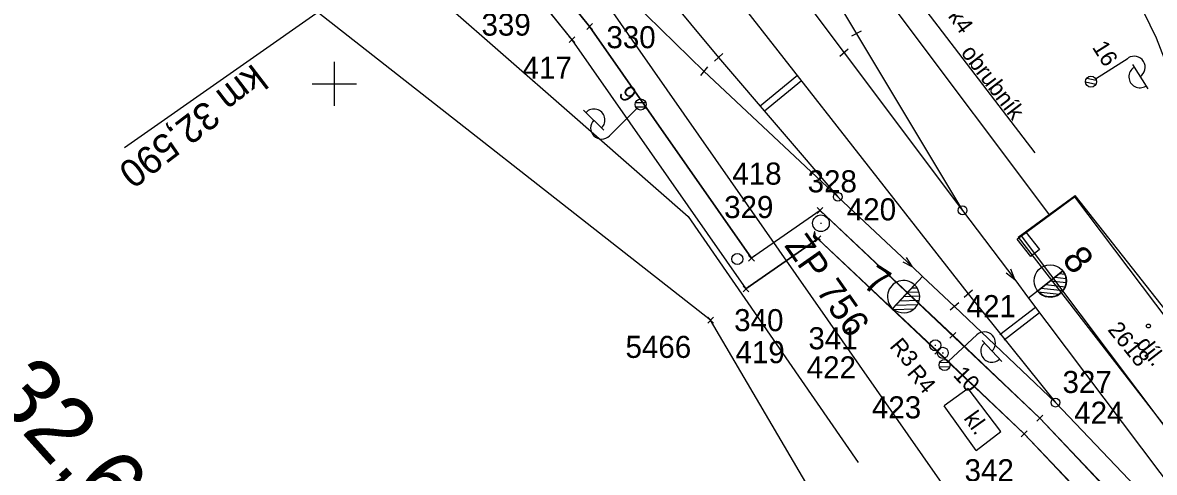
# Model space of a CAD drawing. Extents: x -804166 to -803706, y -1151030 to -1150147.
# Drawn here: x -804028.2 to -803925.7, y -1150435.2 to -1150394.5 of the extents above; entities that cross this region are included whole.
import ezdxf

# ---------------------------------------------------------------- set-up
doc = ezdxf.new("R2010")
doc.units = 0
for name, color, linetype in [('0381KM032-037P - Vrstva 1', 7, 'Continuous'), ('0381KM032-037P - Vrstva 2', 7, 'Continuous'), ('0381KM032-037P - Vrstva 23', 7, 'Continuous'), ('0381KM032-037P - Vrstva 25', 7, 'Continuous'), ('0381KM032-037P - Vrstva 27', 7, 'Continuous'), ('0381KM032-037P - Vrstva 3', 7, 'Continuous'), ('0381KM032-037P - Vrstva 36', 7, 'Continuous'), ('0381KM032-037P - Vrstva 4', 7, 'Continuous'), ('0381KM032-037P - Vrstva 49', 7, 'Continuous'), ('0381KM032-037P - Vrstva 51', 7, 'Continuous'), ('0381KM032-037P - Vrstva 55', 7, 'Continuous'), ('0381KM032-037P - Vrstva 57', 7, 'Continuous'), ('0381KM032-037P - Vrstva 59', 7, 'Continuous'), ('0381KM032-037P - Vrstva 7', 7, 'Continuous'), ('DZ_CD - CD', 7, 'Continuous'), ('DZ_CD - CD_krizek', 7, 'Continuous'), ('DZ_CD - CD_čísla', 7, 'Continuous'), ('krizky_1000 - Vrstva 1', 7, 'Continuous'), ('szdc - hran DP', 7, 'Continuous'), ('szdc - szdc_cislo', 7, 'Continuous'), ('szdc - szdc_krizek', 7, 'Continuous'), ('VB - VB', 7, 'Continuous'), ('VB - VB_cislo', 7, 'Continuous'), ('VB - VB_krizek', 7, 'Continuous'), ('vyt_sit - ohrožené', 7, 'Continuous')]:
    doc.layers.add(name, color=color, linetype=linetype)

msp = doc.modelspace()

# ---------------------------------------------------------------- linework, layer by layer
at = {"layer": '0381KM032-037P - Vrstva 1'}
for points in [[(-804090.39, -1150214.38), (-804086.65, -1150219.55), (-804073.82, -1150237.11), (-804072.56, -1150238.83), (-804064.05, -1150250.31), (-804062.81, -1150251.97), (-804052.29, -1150266.05), (-804042.5, -1150279.11), (-804026.55, -1150300.33), (-804011.27, -1150320.63), (-803993.37, -1150344.49), (-803965.17, -1150382.07), (-803953.84, -1150397.19)], [(-804093.97, -1150217.42), (-804088.17, -1150225.67), (-804077.51, -1150240.28), (-804068.52, -1150252.21), (-804067.31, -1150253.81), (-804055.01, -1150270.12), (-804046.09, -1150281.93), (-804030.05, -1150303.21), (-804014.76, -1150323.52), (-803996.92, -1150347.35), (-803968.88, -1150385.42), (-803942.6, -1150419.03)], [(-804095.55, -1150218.38), (-804090.74, -1150227.08), (-804084.01, -1150238.21), (-804078.76, -1150245.78), (-804072.11, -1150254.85), (-804070.85, -1150256.55), (-804059.97, -1150271.29), (-804049.56, -1150285.37), (-804034.13, -1150306.22), (-804018.79, -1150326.86), (-804001.18, -1150350.63), (-803980.37, -1150378.68), (-803972.82, -1150388.42), (-803965.21, -1150397.6)], [(-803962.12, -1150376.15), (-803948.98, -1150393.6), (-803935.25, -1150411.89)], [(-803963.66, -1150377.12), (-803952.72, -1150395.46)], [(-803974.33, -1150391.21), (-803966.54, -1150398.86)], [(-803975.62, -1150392.3), (-803939.47, -1150444.12), (-803928.27, -1150459.42), (-803914.53, -1150477.73)], [(-803952.72, -1150395.46), (-803943.11, -1150411.46), (-803938.37, -1150417.73), (-803937.13, -1150419.41)], [(-803953.84, -1150397.19), (-803943.11, -1150411.46), (-803938.37, -1150417.73), (-803937.13, -1150419.41)], [(-803965.21, -1150397.6), (-803954.41, -1150410.23), (-803947.65, -1150416.59), (-803946.75, -1150417.44)], [(-803966.54, -1150398.86), (-803954.41, -1150410.23), (-803947.65, -1150416.59), (-803946.75, -1150417.44)], [(-803946.75, -1150417.44), (-803943.83, -1150420.17)], [(-803942.6, -1150419.03), (-803934.7, -1150428.88), (-803926.85, -1150437.12), (-803925.98, -1150438.01)], [(-803937.13, -1150419.41), (-803921.85, -1150439.73)], [(-803943.83, -1150420.17), (-803934.7, -1150428.88), (-803926.85, -1150437.12), (-803925.98, -1150438.01)]]:
    msp.add_lwpolyline(points, dxfattribs=at)
at = {"layer": '0381KM032-037P - Vrstva 2'}
for p, q in [((-803952.28, -1150395.23), (-803953.16, -1150395.69)), ((-803952.72, -1150395.46), (-803943.11, -1150411.46)), ((-803964.83, -1150397.26), (-803965.58, -1150397.93)), ((-803953.46, -1150396.86), (-803954.22, -1150397.51)), ((-803966.22, -1150398.46), (-803966.85, -1150399.25)), ((-803965.21, -1150397.6), (-803954.41, -1150410.23)), ((-803936.33, -1150418.77), (-803934.03, -1150416.95)), ((-803934.03, -1150416.95), (-803936.33, -1150418.77)), ((-803949.43, -1150420.36), (-803946.75, -1150417.44)), ((-803935.16, -1150417.84), (-803933.73, -1150418.01)), ((-803934.75, -1150417.51), (-803933.74, -1150417.63)), ((-803934.33, -1150417.18), (-803933.86, -1150417.24)), ((-803949.44, -1150420.36), (-803947.45, -1150418.21)), ((-803947.04, -1150418.87), (-803948.1, -1150418.91)), ((-803947.21, -1150418.5), (-803947.74, -1150418.52)), ((-803942.22, -1150418.7), (-803942.97, -1150419.36)), ((-803942.6, -1150419.03), (-803934.7, -1150428.88)), ((-803936.33, -1150418.77), (-803937.13, -1150419.41)), ((-803936.33, -1150418.77), (-803936.33, -1150418.77)), ((-803936.25, -1150418.85), (-803934.36, -1150419.07)), ((-803935.99, -1150418.5), (-803934.01, -1150418.73)), ((-803935.58, -1150418.17), (-803933.81, -1150418.38)), ((-803947.18, -1150420.02), (-803949.2, -1150420.09)), ((-803947.03, -1150419.63), (-803948.83, -1150419.7)), ((-803946.99, -1150419.25), (-803948.47, -1150419.3)), ((-803943.45, -1150419.85), (-803944.22, -1150420.49)), ((-803949.44, -1150420.36), (-803949.44, -1150420.36)), ((-803947.52, -1150420.41), (-803949.29, -1150420.48))]:
    msp.add_line(p, q, dxfattribs=at)
for points in [[(-803953.84, -1150397.19), (-803943.11, -1150411.46), (-803938.37, -1150417.73), (-803937.13, -1150419.41)], [(-803966.54, -1150398.86), (-803954.41, -1150410.23), (-803947.65, -1150416.59), (-803946.75, -1150417.44)], [(-803948.53, -1150416.12), (-803947.65, -1150416.59), (-803948.18, -1150415.74)], [(-803939.16, -1150417.11), (-803938.37, -1150417.73), (-803938.75, -1150416.8)], [(-803943.83, -1150420.17), (-803934.7, -1150428.88), (-803926.85, -1150437.12), (-803925.98, -1150438.01)]]:
    msp.add_lwpolyline(points, dxfattribs=at)
for centre, radius in [((-803954.41, -1150410.23), 0.4), ((-803943.11, -1150411.46), 0.4), ((-803935.17, -1150417.85), 1.46), ((-803934.7, -1150428.88), 0.4)]:
    msp.add_circle(centre, radius, dxfattribs=at)
for centre, start, end in [((-803935.18, -1150417.86), 218.5289, 38.4898), ((-803948.45, -1150419.28), 47.1404, 227.6099), ((-803948.45, -1150419.28), 227.2299, 47.1907)]:
    msp.add_arc(centre, 1.46, start, end, dxfattribs=at)
at = {"layer": '0381KM032-037P - Vrstva 23'}
for p, q in [((-803938.07, -1150413.89), (-803932.91, -1150410.13)), ((-803916.52, -1150430.92), (-803932.91, -1150410.13)), ((-803938.07, -1150413.89), (-803921.9, -1150434.82)), ((-803942.6, -1150427.6), (-803944.79, -1150429.16)), ((-803939.63, -1150431.51), (-803942.6, -1150427.6)), ((-803941.89, -1150433.23), (-803944.79, -1150429.16)), ((-803941.89, -1150433.23), (-803939.63, -1150431.51)), ((-803939.63, -1150431.51), (-803939.63, -1150431.51))]:
    msp.add_line(p, q, dxfattribs=at)
at = {"layer": '0381KM032-037P - Vrstva 25'}
for p, q in [((-803931.06, -1150399.53), (-803928.1, -1150397.66)), ((-803927.73, -1150398.25), (-803926.34, -1150400.45)), ((-803931.86, -1150399.47), (-803931.01, -1150399.66)), ((-803931.98, -1150399.83), (-803931.05, -1150400.04)), ((-803975.58, -1150404.21), (-803977.42, -1150402.37)), ((-803972.61, -1150402.23), (-803975.09, -1150404.7)), ((-803971.78, -1150401.73), (-803972.74, -1150401.73)), ((-803971.82, -1150402.11), (-803972.7, -1150402.11)), ((-803944.37, -1150425.14), (-803941.81, -1150422.75)), ((-803941.34, -1150423.26), (-803939.56, -1150425.16)), ((-803945.17, -1150425.23), (-803944.29, -1150425.26)), ((-803945.22, -1150425.6), (-803944.26, -1150425.64))]:
    msp.add_line(p, q, dxfattribs=at)
msp.add_lwpolyline([(-803938.18, -1150414.07), (-803937.39, -1150413.45), (-803936.15, -1150415.02), (-803936.94, -1150415.64), (-803938.18, -1150414.07)], dxfattribs=at)
for centre in [(-803931.48, -1150399.8), (-803931.48, -1150399.8), (-803972.26, -1150401.87), (-803972.26, -1150401.87), (-803944.74, -1150425.48)]:
    msp.add_circle(centre, 0.5, dxfattribs=at)
for centre, start, end in [((-803927.57, -1150398.5), 302.2987, 122.2987), ((-803927.05, -1150399.36), 121.5961, 303.0013), ((-803976.49, -1150403.28), 314.3044, 135.7095), ((-803975.79, -1150404), 135.0069, 315.0069), ((-803941.13, -1150423.48), 313.0804, 133.0804), ((-803940.46, -1150424.22), 132.3778, 313.783)]:
    msp.add_arc(centre, 1, start, end, dxfattribs=at)
at = {"layer": '0381KM032-037P - Vrstva 27'}
for p, q in [((-803945.62, -1150423.69), (-803945.53, -1150423.69)), ((-803944.95, -1150424.37), (-803944.85, -1150424.37))]:
    msp.add_line(p, q, dxfattribs=at)
for centre in [(-803945.58, -1150423.69), (-803944.9, -1150424.37)]:
    msp.add_circle(centre, 0.5, dxfattribs=at)
at = {"layer": '0381KM032-037P - Vrstva 3'}
msp.add_line((-803980.37, -1150378.68), (-804019.01, -1150405.81), dxfattribs=at)
at = {"layer": '0381KM032-037P - Vrstva 36'}
msp.add_circle((-803963.5, -1150415.87), 0.5, dxfattribs=at)
at = {"layer": '0381KM032-037P - Vrstva 4'}
msp.add_lwpolyline([(-804015.09, -1150257.7), (-804005.61, -1150276.65), (-803997.81, -1150289.61), (-803985.99, -1150305.97), (-803963.83, -1150335.54), (-803947.69, -1150357.39), (-803941.6, -1150366.02), (-803933.49, -1150379.54), (-803925.57, -1150395.83), (-803919.57, -1150411.36), (-803915.11, -1150425.7)], dxfattribs=at)
at = {"layer": '0381KM032-037P - Vrstva 49'}
msp.add_lwpolyline([(-803995.51, -1150387.87), (-803978.95, -1150402.37), (-803967.97, -1150412.01), (-803952.57, -1150434.32)], dxfattribs=at)
at = {"layer": '0381KM032-037P - Vrstva 51'}
msp.add_line((-803947.12, -1150392.44), (-803936.56, -1150406.26), dxfattribs=at)
msp.add_lwpolyline([(-804015.09, -1150257.7), (-804005.61, -1150276.65), (-803997.81, -1150289.61), (-803985.99, -1150305.97), (-803963.83, -1150335.54), (-803947.69, -1150357.39), (-803941.6, -1150366.02), (-803933.49, -1150379.54), (-803925.57, -1150395.83), (-803919.57, -1150411.36), (-803915.11, -1150425.7)], dxfattribs=at)
at = {"layer": '0381KM032-037P - Vrstva 55'}
msp.add_lwpolyline([(-803937.77, -1150413.78), (-803932.96, -1150410.23), (-803917.09, -1150431.3), (-803917.49, -1150431.6), (-803915.17, -1150434.66), (-803919.22, -1150437.65), (-803921.53, -1150434.55), (-803921.93, -1150434.85)], close=True, dxfattribs=at)
at = {"layer": '0381KM032-037P - Vrstva 59'}
msp.add_circle((-803926.28, -1150421.94), 0.175, dxfattribs=at)
at = {"layer": '0381KM032-037P - Vrstva 7'}
for p, q in [((-803958.06, -1150399.25), (-803961.44, -1150402.01)), ((-803957.7, -1150399.73), (-803961.05, -1150402.47)), ((-803939.72, -1150422.71), (-803936.51, -1150420.24)), ((-803939.35, -1150423.18), (-803936.15, -1150420.72))]:
    msp.add_line(p, q, dxfattribs=at)
at = {"layer": 'DZ_CD - CD'}
for p, q in [((-803976.88, -1150394.8), (-803989.28, -1150379.42)), ((-803990.89, -1150380.61), (-803978.48, -1150396)), ((-803962.23, -1150415.8), (-803976.88, -1150394.8)), ((-803978.48, -1150396), (-803962.72, -1150418.58)), ((-803956.01, -1150411.47), (-803962.23, -1150415.8)), ((-803936.11, -1150430.3), (-803956.01, -1150411.47)), ((-803962.72, -1150418.58), (-803956.2, -1150414.04)), ((-803956.2, -1150414.04), (-803937.53, -1150431.71)), ((-803913.4, -1150454.32), (-803936.11, -1150430.3)), ((-803937.53, -1150431.71), (-803914.93, -1150455.61))]:
    msp.add_line(p, q, dxfattribs=at)
at = {"layer": 'DZ_CD - CD_krizek'}
for p, q in [((-803976.61, -1150395.06), (-803977.14, -1150394.53)), ((-803977.14, -1150395.06), (-803976.61, -1150394.53)), ((-803978.21, -1150396.26), (-803978.74, -1150395.73)), ((-803978.74, -1150396.26), (-803978.21, -1150395.73)), ((-803955.75, -1150411.74), (-803956.28, -1150411.21)), ((-803956.28, -1150411.74), (-803955.75, -1150411.21)), ((-803955.94, -1150414.3), (-803956.47, -1150413.77)), ((-803956.47, -1150414.3), (-803955.94, -1150413.77)), ((-803961.96, -1150416.07), (-803962.49, -1150415.54)), ((-803962.49, -1150416.07), (-803961.96, -1150415.54)), ((-803962.46, -1150418.85), (-803962.99, -1150418.32)), ((-803962.99, -1150418.85), (-803962.46, -1150418.32)), ((-803935.85, -1150430.56), (-803936.38, -1150430.03)), ((-803936.38, -1150430.56), (-803935.85, -1150430.03)), ((-803937.26, -1150431.98), (-803937.79, -1150431.45)), ((-803937.79, -1150431.98), (-803937.26, -1150431.45))]:
    msp.add_line(p, q, dxfattribs=at)
at = {"layer": 'krizky_1000 - Vrstva 1'}
for points in [[(-804000, -1150398), (-804000, -1150402)], [(-804002, -1150400), (-803998, -1150400)]]:
    msp.add_lwpolyline(points, dxfattribs=at)
at = {"layer": 'szdc - hran DP'}
for p, q in [((-803965.92, -1150421.41), (-804004.05, -1150391.51)), ((-803953.58, -1150442.45), (-803965.92, -1150421.41))]:
    msp.add_line(p, q, dxfattribs=at)
at = {"layer": 'szdc - szdc_krizek'}
for p, q in [((-803965.66, -1150421.68), (-803966.19, -1150421.15)), ((-803966.19, -1150421.68), (-803965.66, -1150421.15))]:
    msp.add_line(p, q, dxfattribs=at)
at = {"layer": 'VB - VB'}
for p, q in [((-803976.88, -1150394.8), (-803962.23, -1150415.8)), ((-803978.48, -1150396), (-803962.72, -1150418.58)), ((-803956.01, -1150411.47), (-803962.23, -1150415.8)), ((-803956.01, -1150411.47), (-803943.99, -1150422.78)), ((-803956.2, -1150414.04), (-803962.72, -1150418.58)), ((-803956.2, -1150414.04), (-803945.37, -1150424.23)), ((-803943.99, -1150422.78), (-803936.11, -1150430.3)), ((-803945.37, -1150424.23), (-803937.53, -1150431.71)), ((-803936.11, -1150430.3), (-803926.23, -1150440.67)), ((-803937.53, -1150431.71), (-803927.68, -1150442.04))]:
    msp.add_line(p, q, dxfattribs=at)
for points in [[(-804005.25, -1150355.72), (-803989.28, -1150379.42), (-803976.88, -1150394.8)], [(-804006.89, -1150356.88), (-803990.89, -1150380.61), (-803978.48, -1150396)]]:
    msp.add_lwpolyline(points, dxfattribs=at)
at = {"layer": 'VB - VB_krizek'}
for p, q in [((-803976.61, -1150395.06), (-803977.14, -1150394.53)), ((-803977.14, -1150395.06), (-803976.61, -1150394.53)), ((-803978.21, -1150396.26), (-803978.74, -1150395.73)), ((-803978.74, -1150396.26), (-803978.21, -1150395.73)), ((-803955.75, -1150411.74), (-803956.28, -1150411.21)), ((-803956.28, -1150411.74), (-803955.75, -1150411.21)), ((-803955.94, -1150414.3), (-803956.47, -1150413.77)), ((-803956.47, -1150414.3), (-803955.94, -1150413.77)), ((-803961.96, -1150416.07), (-803962.49, -1150415.54)), ((-803962.49, -1150416.07), (-803961.96, -1150415.54)), ((-803962.46, -1150418.85), (-803962.99, -1150418.32)), ((-803962.99, -1150418.85), (-803962.46, -1150418.32)), ((-803943.73, -1150423.05), (-803944.26, -1150422.52)), ((-803944.26, -1150423.05), (-803943.73, -1150422.52)), ((-803945.1, -1150424.5), (-803945.63, -1150423.97)), ((-803945.63, -1150424.5), (-803945.1, -1150423.97)), ((-803935.85, -1150430.56), (-803936.38, -1150430.03)), ((-803936.38, -1150430.56), (-803935.85, -1150430.03)), ((-803937.26, -1150431.98), (-803937.79, -1150431.45)), ((-803937.79, -1150431.98), (-803937.26, -1150431.45))]:
    msp.add_line(p, q, dxfattribs=at)
at = {"layer": 'vyt_sit - ohrožené'}
msp.add_line((-803955.98, -1150412.63), (-803955.88, -1150412.63), dxfattribs=at)
msp.add_circle((-803955.93, -1150412.63), 0.756, dxfattribs=at)

# ---------------------------------------------------------------- texts
at = {"layer": '0381KM032-037P - Vrstva 2'}
for s, rotation, p in [('8', 308.5093, (-803934.18, -1150415.96)), ('7', 327.2103, (-803952.28, -1150418.35))]:
    msp.add_text(s, height=2.5, rotation=rotation, dxfattribs=at).set_placement(p)
at = {"layer": '0381KM032-037P - Vrstva 23'}
for s, rotation, p in [('díl.', 307.6769, (-803927.46, -1150423.6)), ('kl.', 305.5697, (-803943.06, -1150430.31))]:
    msp.add_text(s, height=1.5, rotation=rotation, dxfattribs=at).set_placement(p)
at = {"layer": '0381KM032-037P - Vrstva 25'}
for s, rotation, p in [('16', 302.2987, (-803931.42, -1150396.68)), ('9', 310.0069, (-803974.35, -1150400.96)), ('10', 313.0804, (-803944.04, -1150426.44))]:
    msp.add_text(s, height=1.5, rotation=rotation, dxfattribs=at).set_placement(p)
at = {"layer": '0381KM032-037P - Vrstva 27'}
for s, p in [('R3', (-803949.79, -1150423.81)), ('R4', (-803948.21, -1150426.24))]:
    msp.add_text(s, height=1.5, rotation=310, dxfattribs=at).set_placement(p)
at = {"layer": '0381KM032-037P - Vrstva 3'}
for s, height, rotation, p in [('Vk4', 1.5, 305.7164, (-803945.27, -1150392.78)), ('km 32,590', 2.5, 217.4866, (-804007.35, -1150398.11))]:
    msp.add_text(s, height=height, rotation=rotation, dxfattribs=at).set_placement(p)
at = {"layer": '0381KM032-037P - Vrstva 51'}
msp.add_text('obrubník', height=1.5, rotation=307.3807, dxfattribs=at).set_placement((-803943.32, -1150397.19))
at = {"layer": '0381KM032-037P - Vrstva 57'}
msp.add_text('2618', height=1.5, rotation=309.1025, dxfattribs=at).set_placement((-803930.03, -1150422.3))
at = {"layer": '0381KM032-037P - Vrstva 7'}
msp.add_text('32,6', height=6, rotation=311.8828, dxfattribs=at).set_placement((-804031.4, -1150428.19))
at = {"layer": 'DZ_CD - CD_čísla'}
for s, p in [('339', (-803986.67, -1150395.63)), ('330', (-803975.36, -1150396.77)), ('328', (-803957.14, -1150409.83)), ('329', (-803964.7, -1150412.16)), ('340', (-803963.79, -1150422.41)), ('341', (-803957.07, -1150424.05)), ('327', (-803934.06, -1150428.01)), ('342', (-803942.93, -1150436.01))]:
    msp.add_text(s, height=2, dxfattribs=at).set_placement(p)
at = {"layer": 'szdc - szdc_cislo'}
msp.add_text('5466', height=2, dxfattribs=at).set_placement((-803973.63, -1150424.83))
at = {"layer": 'VB - VB_cislo'}
for s, p in [('417', (-803982.95, -1150399.54)), ('418', (-803963.96, -1150409.13)), ('420', (-803953.59, -1150412.37)), ('421', (-803942.74, -1150421.14)), ('419', (-803963.67, -1150425.31)), ('422', (-803957.22, -1150426.69)), ('423', (-803951.32, -1150430.31)), ('424', (-803933, -1150430.8))]:
    msp.add_text(s, height=2, dxfattribs=at).set_placement(p)
at = {"layer": 'vyt_sit - ohrožené'}
msp.add_text('ŽP 756', height=2.4, rotation=305, dxfattribs=at).set_placement((-803959.3, -1150414.66))

doc.saveas('drawing.dxf')
